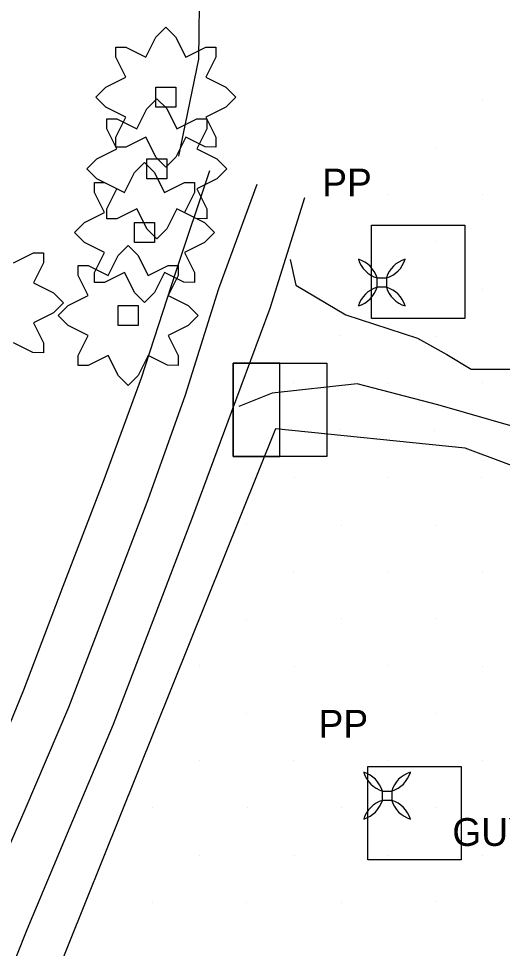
# Model space of a CAD drawing. Extents: x 1602514 to 1609837, y 863887 to 871157.
# Drawn here: x 1605503.5 to 1605612.3, y 865828.9 to 866038 of the extents above; entities that cross this region are included whole.
import ezdxf

# ---------------------------------------------------------------- set-up
doc = ezdxf.new("R2010")
doc.units = 0
for name, color, linetype in [('Environmental-New trees', 7, 'Continuous'), ('Photo-Anchor', 7, 'Continuous'), ('Survey-Centerline', 7, 'Continuous'), ('Survey-Edge of pavement', 7, 'Continuous'), ('Survey-Entrances', 7, 'Continuous'), ('Survey-Ridge Lines', 7, 'Continuous'), ('Survey-Spot dirt', 7, 'Continuous'), ('Survey-Vegetation trees', 7, 'Continuous'), ('Utility-Pole', 7, 'Continuous')]:
    doc.layers.add(name, color=color, linetype=linetype)

msp = doc.modelspace()

# ---------------------------------------------------------------- linework, layer by layer
at = {"layer": 'Environmental-New trees'}
for points in [[(1605525.4, 866031.53), (1605527.65, 866031.53), (1605532.15, 866029.28), (1605534.4, 866033.78), (1605536.65, 866036.03), (1605538.85, 866033.84), (1605541.15, 866029.28), (1605545.66, 866031.53), (1605547.91, 866031.53), (1605547.91, 866029.28), (1605545.66, 866024.78), (1605550.16, 866022.53), (1605552.41, 866020.28), (1605550.16, 866018.03), (1605545.66, 866015.78), (1605547.91, 866011.28), (1605547.91, 866009.03), (1605545.48, 866009.11), (1605541.15, 866011.28), (1605538.9, 866006.78), (1605536.65, 866004.53), (1605534.46, 866006.72), (1605532.15, 866011.28), (1605527.65, 866009.03), (1605525.4, 866009.03), (1605525.4, 866011.28), (1605527.65, 866015.78), (1605523.15, 866018.03), (1605520.9, 866020.28), (1605523.15, 866022.53), (1605527.65, 866024.78), (1605525.4, 866029.28)], [(1605525.4, 866031.53), (1605527.65, 866031.53), (1605532.15, 866029.28), (1605534.4, 866033.78), (1605536.65, 866036.03), (1605538.85, 866033.84), (1605541.15, 866029.28), (1605545.66, 866031.53), (1605547.91, 866031.53), (1605547.91, 866029.28), (1605545.66, 866024.78), (1605550.16, 866022.53), (1605552.41, 866020.28), (1605550.16, 866018.03), (1605545.66, 866015.78), (1605547.91, 866011.28), (1605547.91, 866009.03), (1605545.48, 866009.11), (1605541.15, 866011.28), (1605538.9, 866006.78), (1605536.65, 866004.53), (1605534.46, 866006.72), (1605532.15, 866011.28), (1605527.65, 866009.03), (1605525.4, 866009.03), (1605525.4, 866011.28), (1605527.65, 866015.78), (1605523.15, 866018.03), (1605520.9, 866020.28), (1605523.15, 866022.53), (1605527.65, 866024.78), (1605525.4, 866029.28)], [(1605538.9, 866022.53), (1605538.9, 866018.03), (1605534.4, 866018.03), (1605534.4, 866022.53)], [(1605538.9, 866022.53), (1605538.9, 866018.03), (1605534.4, 866018.03), (1605534.4, 866022.53)], [(1605523.39, 866015.42), (1605525.64, 866015.42), (1605530.14, 866013.17), (1605532.39, 866017.67), (1605534.64, 866019.92), (1605536.83, 866017.73), (1605539.14, 866013.17), (1605543.64, 866015.42), (1605545.89, 866015.42), (1605545.89, 866013.17), (1605543.64, 866008.67), (1605548.14, 866006.42), (1605550.39, 866004.17), (1605548.14, 866001.92), (1605543.64, 865999.67), (1605545.89, 865995.17), (1605545.89, 865992.92), (1605543.46, 865993), (1605539.14, 865995.17), (1605536.89, 865990.67), (1605534.64, 865988.42), (1605532.45, 865990.61), (1605530.14, 865995.17), (1605525.64, 865992.92), (1605523.39, 865992.92), (1605523.39, 865995.17), (1605525.64, 865999.67), (1605521.14, 866001.92), (1605518.89, 866004.17), (1605521.14, 866006.42), (1605525.64, 866008.67), (1605523.39, 866013.17)], [(1605523.39, 866015.42), (1605525.64, 866015.42), (1605530.14, 866013.17), (1605532.39, 866017.67), (1605534.64, 866019.92), (1605536.83, 866017.73), (1605539.14, 866013.17), (1605543.64, 866015.42), (1605545.89, 866015.42), (1605545.89, 866013.17), (1605543.64, 866008.67), (1605548.14, 866006.42), (1605550.39, 866004.17), (1605548.14, 866001.92), (1605543.64, 865999.67), (1605545.89, 865995.17), (1605545.89, 865992.92), (1605543.46, 865993), (1605539.14, 865995.17), (1605536.89, 865990.67), (1605534.64, 865988.42), (1605532.45, 865990.61), (1605530.14, 865995.17), (1605525.64, 865992.92), (1605523.39, 865992.92), (1605523.39, 865995.17), (1605525.64, 865999.67), (1605521.14, 866001.92), (1605518.89, 866004.17), (1605521.14, 866006.42), (1605525.64, 866008.67), (1605523.39, 866013.17)], [(1605536.89, 866006.42), (1605536.89, 866001.92), (1605532.39, 866001.92), (1605532.39, 866006.42)], [(1605536.89, 866006.42), (1605536.89, 866001.92), (1605532.39, 866001.92), (1605532.39, 866006.42)], [(1605520.58, 866001.11), (1605522.83, 866001.11), (1605527.33, 865998.86), (1605529.58, 866003.36), (1605531.83, 866005.61), (1605534.02, 866003.42), (1605536.33, 865998.86), (1605540.83, 866001.11), (1605543.08, 866001.11), (1605543.08, 865998.86), (1605540.83, 865994.36), (1605545.33, 865992.11), (1605547.58, 865989.86), (1605545.33, 865987.61), (1605540.83, 865985.36), (1605543.08, 865980.86), (1605543.08, 865978.61), (1605540.65, 865978.69), (1605536.33, 865980.86), (1605534.08, 865976.35), (1605531.83, 865974.1), (1605529.64, 865976.3), (1605527.33, 865980.86), (1605522.83, 865978.61), (1605520.58, 865978.61), (1605520.58, 865980.86), (1605522.83, 865985.36), (1605518.33, 865987.61), (1605516.08, 865989.86), (1605518.33, 865992.11), (1605522.83, 865994.36), (1605520.58, 865998.86)], [(1605520.58, 866001.11), (1605522.83, 866001.11), (1605527.33, 865998.86), (1605529.58, 866003.36), (1605531.83, 866005.61), (1605534.02, 866003.42), (1605536.33, 865998.86), (1605540.83, 866001.11), (1605543.08, 866001.11), (1605543.08, 865998.86), (1605540.83, 865994.36), (1605545.33, 865992.11), (1605547.58, 865989.86), (1605545.33, 865987.61), (1605540.83, 865985.36), (1605543.08, 865980.86), (1605543.08, 865978.61), (1605540.65, 865978.69), (1605536.33, 865980.86), (1605534.08, 865976.35), (1605531.83, 865974.1), (1605529.64, 865976.3), (1605527.33, 865980.86), (1605522.83, 865978.61), (1605520.58, 865978.61), (1605520.58, 865980.86), (1605522.83, 865985.36), (1605518.33, 865987.61), (1605516.08, 865989.86), (1605518.33, 865992.11), (1605522.83, 865994.36), (1605520.58, 865998.86)], [(1605534.08, 865992.11), (1605534.08, 865987.61), (1605529.58, 865987.61), (1605529.58, 865992.11)], [(1605534.08, 865992.11), (1605534.08, 865987.61), (1605529.58, 865987.61), (1605529.58, 865992.11)], [(1605516.91, 865982.45), (1605519.16, 865982.45), (1605523.66, 865980.2), (1605525.91, 865984.7), (1605528.16, 865986.95), (1605530.36, 865984.76), (1605532.66, 865980.2), (1605537.17, 865982.45), (1605539.42, 865982.45), (1605539.42, 865980.2), (1605537.17, 865975.7), (1605541.67, 865973.45), (1605543.92, 865971.2), (1605541.67, 865968.95), (1605537.17, 865966.7), (1605539.42, 865962.19), (1605539.42, 865959.94), (1605536.99, 865960.03), (1605532.66, 865962.19), (1605530.41, 865957.69), (1605528.16, 865955.44), (1605525.97, 865957.64), (1605523.66, 865962.19), (1605519.16, 865959.94), (1605516.91, 865959.94), (1605516.91, 865962.19), (1605519.16, 865966.7), (1605514.66, 865968.95), (1605512.41, 865971.2), (1605514.66, 865973.45), (1605519.16, 865975.7), (1605516.91, 865980.2)], [(1605516.91, 865982.45), (1605519.16, 865982.45), (1605523.66, 865980.2), (1605525.91, 865984.7), (1605528.16, 865986.95), (1605530.36, 865984.76), (1605532.66, 865980.2), (1605537.17, 865982.45), (1605539.42, 865982.45), (1605539.42, 865980.2), (1605537.17, 865975.7), (1605541.67, 865973.45), (1605543.92, 865971.2), (1605541.67, 865968.95), (1605537.17, 865966.7), (1605539.42, 865962.19), (1605539.42, 865959.94), (1605536.99, 865960.03), (1605532.66, 865962.19), (1605530.41, 865957.69), (1605528.16, 865955.44), (1605525.97, 865957.64), (1605523.66, 865962.19), (1605519.16, 865959.94), (1605516.91, 865959.94), (1605516.91, 865962.19), (1605519.16, 865966.7), (1605514.66, 865968.95), (1605512.41, 865971.2), (1605514.66, 865973.45), (1605519.16, 865975.7), (1605516.91, 865980.2)], [(1605530.41, 865973.45), (1605530.41, 865968.95), (1605525.91, 865968.95), (1605525.91, 865973.45)], [(1605530.41, 865973.45), (1605530.41, 865968.95), (1605525.91, 865968.95), (1605525.91, 865973.45)]]:
    msp.add_lwpolyline(points, close=True, dxfattribs=at)
msp.add_lwpolyline([(1605502.38, 865983.05), (1605506.88, 865985.3), (1605509.13, 865985.3), (1605509.13, 865983.05), (1605506.88, 865978.55), (1605511.38, 865976.3), (1605513.63, 865974.04), (1605511.38, 865971.79), (1605506.88, 865969.54), (1605509.13, 865965.04), (1605509.13, 865962.79), (1605506.71, 865962.88), (1605502.38, 865965.04)], dxfattribs=at)
msp.add_lwpolyline([(1605502.38, 865983.05), (1605506.88, 865985.3), (1605509.13, 865985.3), (1605509.13, 865983.05), (1605506.88, 865978.55), (1605511.38, 865976.3), (1605513.63, 865974.04), (1605511.38, 865971.79), (1605506.88, 865969.54), (1605509.13, 865965.04), (1605509.13, 865962.79), (1605506.71, 865962.88), (1605502.38, 865965.04)], dxfattribs=at)
at = {"layer": 'Photo-Anchor'}
for points in [[(1605584.14, 865979.65), (1605586.24, 865979.65), (1605586.24, 865977.55), (1605584.14, 865977.55)], [(1605584.14, 865979.65), (1605586.24, 865979.65), (1605586.24, 865977.55), (1605584.14, 865977.55)], [(1605585.33, 865864.3), (1605587.43, 865864.3), (1605587.43, 865862.2), (1605585.33, 865862.2)], [(1605585.33, 865864.3), (1605587.43, 865864.3), (1605587.43, 865862.2), (1605585.33, 865862.2)]]:
    msp.add_lwpolyline(points, close=True, dxfattribs=at)
for centre, radius, start, end in [((1605578.13, 865977.85), 6.27, 16.7236, 73.2821), ((1605585.95, 865985.67), 6.29, 196.8106, 253.1951), ((1605578.13, 865977.85), 6.27, 16.7236, 73.2821), ((1605585.95, 865985.67), 6.29, 196.8106, 253.1951), ((1605592.24, 865977.85), 6.27, 106.7179, 163.2764), ((1605584.42, 865985.67), 6.29, 286.8049, 343.1894), ((1605592.24, 865977.85), 6.27, 106.7179, 163.2764), ((1605584.42, 865985.67), 6.29, 286.8049, 343.1894), ((1605578.13, 865979.36), 6.27, 286.7179, 343.2764), ((1605585.95, 865971.54), 6.29, 106.8049, 163.1894), ((1605578.13, 865979.36), 6.27, 286.7179, 343.2764), ((1605585.95, 865971.54), 6.29, 106.8049, 163.1894), ((1605592.24, 865979.36), 6.27, 196.7236, 253.2821), ((1605584.42, 865971.54), 6.29, 16.8106, 73.1951), ((1605592.24, 865979.36), 6.27, 196.7236, 253.2821), ((1605584.42, 865971.54), 6.29, 16.8106, 73.1951), ((1605579.33, 865862.5), 6.27, 16.7236, 73.2821), ((1605587.15, 865870.32), 6.29, 196.8106, 253.1951), ((1605579.33, 865862.5), 6.27, 16.7236, 73.2821), ((1605587.15, 865870.32), 6.29, 196.8106, 253.1951), ((1605593.43, 865862.5), 6.27, 106.7179, 163.2764), ((1605585.61, 865870.32), 6.29, 286.8049, 343.1894), ((1605593.43, 865862.5), 6.27, 106.7179, 163.2764), ((1605585.61, 865870.32), 6.29, 286.8049, 343.1894), ((1605579.33, 865864.01), 6.27, 286.7179, 343.2764), ((1605587.15, 865856.18), 6.29, 106.8049, 163.1894), ((1605579.33, 865864.01), 6.27, 286.7179, 343.2764), ((1605587.15, 865856.18), 6.29, 106.8049, 163.1894), ((1605593.43, 865864.01), 6.27, 196.7236, 253.2821), ((1605585.61, 865856.18), 6.29, 16.8106, 73.1951), ((1605593.43, 865864.01), 6.27, 196.7236, 253.2821), ((1605585.61, 865856.18), 6.29, 16.8106, 73.1951)]:
    msp.add_arc(centre, radius, start, end, dxfattribs=at)
at = {"layer": 'Survey-Centerline'}
msp.add_lwpolyline([(1605557.12, 866000.67), (1605548.5, 865977.21), (1605540.97, 865953.33), (1605532.59, 865929.77), (1605523.67, 865906.42), (1605514.77, 865883.07), (1605504.97, 865860.05), (1605494.9, 865837.14), (1605484.31, 865814.41), (1605476.69, 865790.58), (1605468.58, 865766.93), (1605461, 865743.1), (1605455.2, 865718.83)], dxfattribs=at)
msp.add_lwpolyline([(1605557.12, 866000.67), (1605548.5, 865977.21), (1605540.97, 865953.33), (1605532.59, 865929.77), (1605523.67, 865906.42), (1605514.77, 865883.07), (1605504.97, 865860.05), (1605494.9, 865837.14), (1605484.31, 865814.41), (1605476.69, 865790.58), (1605468.58, 865766.93), (1605461, 865743.1), (1605455.2, 865718.83)], dxfattribs=at)
at = {"layer": 'Survey-Edge of pavement'}
for points in [[(1605546.44, 866003.73), (1605538.85, 865980.9), (1605531.12, 865957.09), (1605522.44, 865933.66), (1605513.51, 865910.31), (1605504.61, 865886.95), (1605495.14, 865863.81), (1605485.62, 865840.69), (1605476.01, 865817.46), (1605467.72, 865793.87), (1605458.66, 865769.94), (1605451.08, 865746.11), (1605444.91, 865720.09)], [(1605546.44, 866003.73), (1605538.85, 865980.9), (1605531.12, 865957.09), (1605522.44, 865933.66), (1605513.51, 865910.31), (1605504.61, 865886.95), (1605495.14, 865863.81), (1605485.62, 865840.69), (1605476.01, 865817.46), (1605467.72, 865793.87), (1605458.66, 865769.94), (1605451.08, 865746.11), (1605444.91, 865720.09)], [(1605567.8, 865997.62), (1605560.03, 865972.8), (1605551.35, 865949.36), (1605542.63, 865925.93), (1605533.71, 865902.59), (1605524.81, 865879.23), (1605515.03, 865856.21), (1605505.42, 865833.13), (1605496.14, 865810.07), (1605487.21, 865786.72), (1605478.96, 865763.78), (1605471.39, 865739.95), (1605465.97, 865717.51)], [(1605567.8, 865997.62), (1605560.03, 865972.8), (1605551.35, 865949.36), (1605542.63, 865925.93), (1605533.71, 865902.59), (1605524.81, 865879.23), (1605515.03, 865856.21), (1605505.42, 865833.13), (1605496.14, 865810.07), (1605487.21, 865786.72), (1605478.96, 865763.78), (1605471.39, 865739.95), (1605465.97, 865717.51)]]:
    msp.add_lwpolyline(points, dxfattribs=at)
at = {"layer": 'Survey-Entrances'}
for points in [[(1605564.63, 865983.78), (1605565.85, 865978), (1605577.14, 865971.34), (1605593.23, 865966.14), (1605599.81, 865962.4), (1605605.33, 865959.15), (1605615.08, 865959.15)], [(1605564.63, 865983.78), (1605565.85, 865978), (1605577.14, 865971.34), (1605593.23, 865966.14), (1605599.81, 865962.4), (1605605.33, 865959.15), (1605615.08, 865959.15)], [(1605621.25, 865944.35), (1605597.77, 865951.1), (1605579.66, 865955.81), (1605560.57, 865953.78), (1605553.09, 865950.77)], [(1605621.25, 865944.35), (1605597.77, 865951.1), (1605579.66, 865955.81), (1605560.57, 865953.78), (1605553.09, 865950.77)]]:
    msp.add_lwpolyline(points, dxfattribs=at)
at = {"layer": 'Survey-Ridge Lines'}
msp.add_lwpolyline([(1605544.24, 866047.18), (1605544.02, 866028.85), (1605539.5, 866007.03)], dxfattribs=at)
msp.add_lwpolyline([(1605544.24, 866047.18), (1605544.02, 866028.85), (1605539.5, 866007.03)], dxfattribs=at)
at = {"layer": 'Survey-Spot dirt'}
for p, q in [((1605607.8, 866019.62), (1605607.8, 866019.62)), ((1605607.8, 866019.62), (1605607.8, 866019.62)), ((1605597.33, 866009.08), (1605597.33, 866009.08)), ((1605597.33, 866009.08), (1605597.33, 866009.08)), ((1605586.69, 865998.45), (1605586.69, 865998.45)), ((1605586.69, 865998.45), (1605586.69, 865998.45)), ((1605607.84, 865998.46), (1605607.84, 865998.46)), ((1605607.84, 865998.46), (1605607.84, 865998.46)), ((1605597.19, 865987.9), (1605597.19, 865987.9)), ((1605597.19, 865987.9), (1605597.19, 865987.9)), ((1605586.7, 865977.28), (1605586.7, 865977.28)), ((1605586.7, 865977.28), (1605586.7, 865977.28)), ((1605607.92, 865977.13), (1605607.92, 865977.13)), ((1605607.92, 865977.13), (1605607.92, 865977.13)), ((1605576.02, 865966.62), (1605576.02, 865966.62)), ((1605576.02, 865966.62), (1605576.02, 865966.62)), ((1605597.33, 865966.44), (1605597.33, 865966.44)), ((1605597.33, 865966.44), (1605597.33, 865966.44)), ((1605565.43, 865956.07), (1605565.43, 865956.07)), ((1605565.43, 865956.07), (1605565.43, 865956.07)), ((1605607.77, 865956.14), (1605607.77, 865956.14)), ((1605607.77, 865956.14), (1605607.77, 865956.14)), ((1605586.63, 865955.95), (1605586.63, 865955.95)), ((1605586.63, 865955.95), (1605586.63, 865955.95)), ((1605575.99, 865945.48), (1605575.99, 865945.48)), ((1605575.99, 865945.48), (1605575.99, 865945.48)), ((1605597.15, 865945.42), (1605597.15, 865945.42)), ((1605597.15, 865945.42), (1605597.15, 865945.42)), ((1605565.5, 865934.73), (1605565.5, 865934.73)), ((1605565.5, 865934.73), (1605565.5, 865934.73)), ((1605586.61, 865934.76), (1605586.61, 865934.76)), ((1605586.61, 865934.76), (1605586.61, 865934.76)), ((1605607.71, 865934.83), (1605607.71, 865934.83)), ((1605607.71, 865934.83), (1605607.71, 865934.83)), ((1605554.8, 865924.24), (1605554.8, 865924.24)), ((1605554.8, 865924.24), (1605554.8, 865924.24)), ((1605576.13, 865924.09), (1605576.13, 865924.09)), ((1605576.13, 865924.09), (1605576.13, 865924.09)), ((1605597.29, 865924.06), (1605597.29, 865924.06)), ((1605597.29, 865924.06), (1605597.29, 865924.06)), ((1605565.43, 865913.49), (1605565.43, 865913.49)), ((1605565.43, 865913.49), (1605565.43, 865913.49)), ((1605586.62, 865913.53), (1605586.62, 865913.53)), ((1605586.62, 865913.53), (1605586.62, 865913.53)), ((1605607.85, 865913.6), (1605607.85, 865913.6)), ((1605607.85, 865913.6), (1605607.85, 865913.6)), ((1605554.84, 865902.96), (1605554.84, 865902.96)), ((1605554.84, 865902.96), (1605554.84, 865902.96)), ((1605576.11, 865902.98), (1605576.11, 865902.98)), ((1605576.11, 865902.98), (1605576.11, 865902.98)), ((1605597.3, 865903.05), (1605597.3, 865903.05)), ((1605597.3, 865903.05), (1605597.3, 865903.05)), ((1605544.22, 865892.47), (1605544.22, 865892.47)), ((1605544.22, 865892.47), (1605544.22, 865892.47)), ((1605565.47, 865892.39), (1605565.47, 865892.39)), ((1605565.47, 865892.39), (1605565.47, 865892.39)), ((1605586.55, 865892.43), (1605586.55, 865892.43)), ((1605586.55, 865892.43), (1605586.55, 865892.43)), ((1605607.9, 865892.32), (1605607.9, 865892.32)), ((1605607.9, 865892.32), (1605607.9, 865892.32)), ((1605533.79, 865881.79), (1605533.79, 865881.79)), ((1605533.79, 865881.79), (1605533.79, 865881.79)), ((1605554.77, 865881.78), (1605554.77, 865881.78)), ((1605554.77, 865881.78), (1605554.77, 865881.78)), ((1605576.03, 865881.75), (1605576.03, 865881.75)), ((1605576.03, 865881.75), (1605576.03, 865881.75)), ((1605597.31, 865881.62), (1605597.31, 865881.62)), ((1605597.31, 865881.62), (1605597.31, 865881.62)), ((1605544.13, 865871.17), (1605544.13, 865871.17)), ((1605544.13, 865871.17), (1605544.13, 865871.17)), ((1605565.3, 865871.25), (1605565.3, 865871.25)), ((1605565.3, 865871.25), (1605565.3, 865871.25)), ((1605586.57, 865871.12), (1605586.57, 865871.12)), ((1605586.57, 865871.12), (1605586.57, 865871.12)), ((1605607.85, 865871.19), (1605607.85, 865871.19)), ((1605607.85, 865871.19), (1605607.85, 865871.19)), ((1605533.71, 865860.59), (1605533.71, 865860.59)), ((1605533.71, 865860.59), (1605533.71, 865860.59)), ((1605554.95, 865860.53), (1605554.95, 865860.53)), ((1605554.95, 865860.53), (1605554.95, 865860.53)), ((1605576.17, 865860.5), (1605576.17, 865860.5)), ((1605576.17, 865860.5), (1605576.17, 865860.5)), ((1605597.33, 865860.5), (1605597.33, 865860.5)), ((1605597.33, 865860.5), (1605597.33, 865860.5)), ((1605523.06, 865850.01), (1605523.06, 865850.01)), ((1605523.06, 865850.01), (1605523.06, 865850.01)), ((1605544.22, 865849.87), (1605544.22, 865849.87)), ((1605544.22, 865849.87), (1605544.22, 865849.87)), ((1605565.51, 865849.91), (1605565.51, 865849.91)), ((1605565.51, 865849.91), (1605565.51, 865849.91)), ((1605586.73, 865849.89), (1605586.73, 865849.89)), ((1605586.73, 865849.89), (1605586.73, 865849.89)), ((1605607.83, 865849.84), (1605607.83, 865849.84)), ((1605607.83, 865849.84), (1605607.83, 865849.84)), ((1605533.55, 865839.31), (1605533.55, 865839.31)), ((1605533.55, 865839.31), (1605533.55, 865839.31)), ((1605554.88, 865839.26), (1605554.88, 865839.26)), ((1605554.88, 865839.26), (1605554.88, 865839.26)), ((1605576.1, 865839.28), (1605576.1, 865839.28)), ((1605576.1, 865839.28), (1605576.1, 865839.28)), ((1605597.39, 865839.39), (1605597.39, 865839.39)), ((1605597.39, 865839.39), (1605597.39, 865839.39))]:
    msp.add_line(p, q, dxfattribs=at)
at = {"layer": 'Survey-Vegetation trees'}
msp.add_lwpolyline([(1605710.65, 865516.6), (1605651, 865843.77), (1605647.08, 865925.24), (1605603.98, 865941.36), (1605561.31, 865945.71), (1605506.89, 865810.23), (1605475.11, 865704.36)], dxfattribs=at)
msp.add_lwpolyline([(1605710.65, 865516.6), (1605651, 865843.77), (1605647.08, 865925.24), (1605603.98, 865941.36), (1605561.31, 865945.71), (1605506.89, 865810.23), (1605475.11, 865704.36)], dxfattribs=at)
at = {"layer": 'Utility-Pole'}
for points in [[(1605582.87, 865991.5), (1605603.88, 865991.5), (1605603.88, 865970.5), (1605582.87, 865970.5)], [(1605582.87, 865991.5), (1605603.88, 865991.5), (1605603.88, 865970.5), (1605582.87, 865970.5)], [(1605551.81, 865939.47), (1605562.31, 865939.47), (1605562.31, 865960.47), (1605551.81, 865960.47)], [(1605551.81, 865960.47), (1605572.82, 865960.47), (1605572.82, 865939.47), (1605551.81, 865939.47)], [(1605551.81, 865939.47), (1605562.31, 865939.47), (1605562.31, 865960.47), (1605551.81, 865960.47)], [(1605551.81, 865960.47), (1605572.82, 865960.47), (1605572.82, 865939.47), (1605551.81, 865939.47)], [(1605582.04, 865869.81), (1605603.04, 865869.81), (1605603.04, 865848.8), (1605582.04, 865848.8)], [(1605582.04, 865869.81), (1605603.04, 865869.81), (1605603.04, 865848.8), (1605582.04, 865848.8)]]:
    msp.add_lwpolyline(points, close=True, dxfattribs=at)

# ---------------------------------------------------------------- texts
for s, p in [('PP', (1605571.81, 865997.97)), ('PP', (1605571.81, 865997.97)), ('PP', (1605570.98, 865876.28)), ('PP', (1605570.98, 865876.28)), ('GUY', (1605601.07, 865851.96)), ('GUY', (1605601.07, 865851.96))]:
    msp.add_text(s, height=6.251, dxfattribs=at).set_placement(p)

doc.saveas('drawing.dxf')
